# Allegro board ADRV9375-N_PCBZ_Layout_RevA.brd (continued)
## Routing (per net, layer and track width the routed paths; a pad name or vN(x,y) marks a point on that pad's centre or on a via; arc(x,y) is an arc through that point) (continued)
SNRXA-: length 16.3
  TOP w0.254: U101.D4 v6(30.84,43.58)
  L10_SIG w0.091: v6(30.84,43.58) 31.12,43.58 arc(31.24,43.53) 31.28,43.42 arc(31.29,43.36) 31.33,43.31 31.38,43.26 arc(31.42,43.16) 31.38,43.07 31.28,42.97 arc(31.22,42.88) 31.2,42.78 arc(31.21,42.74) 31.23,42.71 31.42,42.51 arc(31.46,42.46) 31.47,42.4 arc(31.46,42.31) 31.41,42.24 31.25,42.08 arc(31.21,42.03) 31.2,41.96 arc(31.16,41.78) 31.06,41.62 arc(30.92,41.53) 30.76,41.5 30.6,41.5 arc(30.13,41.3) 29.93,40.83 29.93,36.18 arc(29.84,35.73) 29.59,35.35 29.53,35.29 arc(29.14,34.81) 28.87,34.25 arc(28.41,32.9) 28,31.53 arc(27.91,31.35) v5(27.75,31.22)
  BOTTOM w0.203: C223.2 27.19,29.74 arc(27.3,29.82) 27.37,29.94 ; C224.2 L224.2 27.71,30.93 arc(27.74,31.07) v5(27.75,31.22)
SPI_CLK: length 112.3
  TOP w0.254: U405.3 120.14,60.64 121.68,59.1 121.68,58.09 120.48,56.9 TP802.1 ; U101.K9 v6(36.44,48.38)
  TOP w0.305: TP802.1 121.34,54.91 129.9,54.91 131.17,56.17 R804.1
  L7_SIG w0.114: TP802.1 119,54.28 104.66,54.28 100.72,58.21 93.1,58.21 v8(92.85,57.96)
  L8_SIG w0.114: v6(36.44,48.38) 36.69,48.38 37.08,47.99 41.22,47.99 41.41,48.18 46,48.18 47.19,49.37 49.84,49.37 50.68,50.21 65.67,50.21 73.42,57.96 v8(92.85,57.96)
SPI_CLK_9528: length 44.4
  TOP w0.203: U405.12 120.14,66.45 v1(119.77,66.09)
  L7_SIG w0.114: v1(119.77,66.09) 119.35,66.51 119.35,66.51 119.05,66.81 119.05,66.81 119.01,66.85 118.75,66.85 116.28,69.33 96.08,69.33 93.74,71.67 84.47,71.67 83.56,70.76 82.44,70.76 v1(82.21,70.99)
  BOTTOM w0.254: U401.22 83.47,70.83 83.38,70.74 82.46,70.74 v1(82.21,70.99)
SPI_CS0: length 120.1
  TOP w0.254: R811.1 R808.2 138.55,55.23 138.89,55.57 v2(139.1,55.57) ; U101.K10 v6(36.44,49.18) ; TP813.1 119.9,58.69 118.65,59.94 117.33,59.94 116.71,60.56 U403.7
  L7_SIG w0.114: TP813.1 119.34,57.54 116.88,57.54 115.13,55.8 105.67,55.8 101.86,59.61 89.42,59.61 v8(89.04,59.23)
  L8_SIG w0.114: v6(36.44,49.18) 36.84,49.58 40.01,49.58 40.52,50.08 43.11,50.08 43.27,49.93 43.61,49.93 43.9,50.21 45.2,50.21 46.85,51.86 63.89,51.86 72.27,60.24 85.35,60.24 86.37,59.23 v8(89.04,59.23)
  L8_SIG w0.254: TP813.1 122.99,56.18 138.49,56.18 v2(139.1,55.57)
SPI_CS1: length 37
  TOP w0.254: 121.44,63.18 U405.5 ; U403.1 117.21,64.54 117.48,64.82
  TOP w0.305: 117.48,64.82 117.7,65.03 119.58,65.03 121.44,63.18 121.93,63.67 124.09,63.67 TP814.1 127.34,62.4 127.52,62.23 130.41,62.23 130.74,62.56 136.69,62.56 137.12,62.12 137.12,52.75 137.5,52.37 138.21,52.37 138.55,52.71 R809.2 R812.1
SPI_CS_9528: length 47
  TOP w0.203: U405.10 121.44,66.07 v1(121.68,65.83)
  L7_SIG w0.114: v1(81.7,70.25) 93.12,70.25 95.2,68.18 115.77,68.18 118.75,65.2 121.04,65.2 v1(121.68,65.83)
  BOTTOM w0.254: v1(81.7,70.25) 83.62,70.25 83.69,70.33 83.78,70.33 U401.21
SPI_DIN: length 114.3
  TOP w0.254: U405.4 120.79,60.88 123,58.66 TP801.1 ; U101.J9 v6(35.64,48.38)
  TOP w0.305: TP801.1 125.39,56.68 129.45,56.68 130.14,57.37 R805.1
  L7_SIG w0.114: v1(83.96,59.36) 84.03,59.36 85.56,60.88 87.17,60.88 87.17,60.89 87.6,60.89 87.6,60.88 96.59,60.88 96.97,60.5 102.24,60.5 106.18,56.56 113.93,56.56 117.4,60.03 122.03,60.03 TP801.1
  L8_SIG w0.114: v1(83.96,59.36) 83.91,59.4 72.96,59.4 64.65,51.1 47,51.1 45.27,49.37 40.95,49.37 40.34,48.76 36.03,48.76 v6(35.64,48.38)
SPI_DIN_9528: length 43.6
  TOP w0.203: U405.11 v1(120.79,66.34)
  L7_SIG w0.114: v1(120.79,66.34) 120.79,66.47 116.85,70.4 96.53,70.4 93.86,73.07 85.02,73.07 v1(83.28,71.33)
  BOTTOM w0.254: U401.23 83.68,71.33 v1(83.28,71.33)
SPI_DOUT: length 31.6
  TOP w0.203: TP809.1 117.59,58.69 ; 116.2,61.33 U403.6
  TOP w0.254: R806.1 136.06,55.72 136.06,55.71 136.06,55.45 135.47,54.86 130.95,54.86 130.23,54.15 119.47,54.15 118.66,54.96 118.66,57.62 116.19,60.09 116.19,61.32 116.21,61.35 U403.3
SPI_DOUT_9370: length 91.9
  TOP w0.254: U101.J10 v6(35.64,49.18) ; TP402.1 116.07,57.26 R427.2
  L7_SIG w0.097: 39.89,46.39 39.49,46.39
  L7_SIG w0.114: 39.49,46.39 37.95,46.39 37.7,46.64 37.7,47.06 37.58,47.19 37.08,47.19 36.85,47.42 36.85,47.74 36.55,48.04 36.3,48.04 36.1,48.24 36.1,48.66 35.64,49.13 v6(35.64,49.18) ; 39.89,46.39 42.88,46.39 43.41,46.92 44.45,46.92 45.18,46.19 48.52,46.19 48.61,46.11 75.41,46.11 77.1,47.8 77.63,47.8 79.64,49.81 v1(79.64,50.08)
  BOTTOM w0.394: TP402.1 111.83,50.08 v1(79.64,50.08)
SPI_DOUT_9528: length 40.5
  TOP w0.254: R426.2 111.83,71.17 101.36,71.17 TP401.1
  L7_SIG w0.114: TP401.1 96.91,71.55 94.12,74.34 85.25,74.34 v1(82.56,71.65)
  BOTTOM w0.254: v1(82.56,71.65) 82.83,71.91 83.59,71.91 83.67,71.83 83.81,71.83 U401.24
STATUS_0: length 25.1
  L5_SIG w0.114: v1(96.53,79.96) 96.19,80.3 77.85,80.3 v1(77.25,79.7)
  BOTTOM w0.254: U401.55 94.81,77.83 95.9,78.92 95.9,79.32 v1(96.53,79.96) ; R418.1 97.17,79.96
  BOTTOM w0.305: v1(77.25,79.7) 76.64,79.7 76.63,79.69 U402.1
  BOTTOM w0.394: 97.17,79.96 v1(96.53,79.96)
STATUS_1: length 24.5
  L5_SIG w0.114: v1(77.25,78.38) 77.76,78.89 v1(96.53,78.89)
  BOTTOM w0.203: R419.1 97.17,78.89
  BOTTOM w0.254: v1(96.53,78.89) 96.53,78.83 95.03,77.33 U401.56
  BOTTOM w0.305: v1(77.25,78.38) 76.64,78.38 76.63,78.39 U402.3
  BOTTOM w0.394: 97.17,78.89 v1(96.53,78.89)
SYNCINB0+: length 150.5
  TOP w0.254: U101.M4 v6(38.04,43.58)
  L7_SIG w0.091: v6(38.04,43.58) 38.04,43.25 37.71,42.91 37.71,41.85 37.93,41.62 39.84,41.62 40.77,40.68 44.84,40.68 48.14,37.38 59.68,37.38 60.57,38.27 105.19,38.27 110.14,33.32 111.79,33.32 113.19,31.92 116.24,31.92 119.66,28.49 126.63,28.49 127.14,29 ; 127.14,29 127.77,29.64 132.45,29.64 136.77,33.96 137.78,33.96 139.91,36.09 139.91,39.2 141.36,40.65 141.97,40.65 143.75,42.43 143.75,60.77 143.14,61.39 137.02,61.39 v2(136.56,61.85) ; 127.14,29 TP807.1
  BOTTOM w0.203: P801.G9 v2(136.56,61.85)
SYNCINB0-: length 150.5
  TOP w0.254: U101.M3 v6(38.04,42.78)
  L7_SIG w0.091: 127.02,29.24 126.96,29.18 126.96,29.18 126.52,28.75 119.77,28.75 116.34,32.18 113.29,32.18 111.9,33.57 110.25,33.57 105.29,38.53 60.46,38.53 59.57,37.64 48.25,37.64 44.95,40.94 40.87,40.94 40.09,41.72 40.09,42.16 39.93,42.32 38.14,42.32 38.04,42.42 v6(38.04,42.78) ; 127.02,29.24 126.89,29.24 126.14,29.99 TP808.1 ; 127.02,29.24 127.67,29.89 132.34,29.89 136.66,34.21 137.68,34.21 139.66,36.19 139.66,39.31 141.26,40.91 141.87,40.91 143.5,42.54 143.5,60.67 143.03,61.14 136.92,61.14 136.66,61.39 135.9,61.39 135.77,61.26 135.77,60.58 135.9,60.45 136.44,60.45 136.56,60.58 v2(136.56,60.58)
  BOTTOM w0.203: P801.G10 v2(136.56,60.58)
SYNCINB1+: length 108.7
  TOP w0.254: U101.L4 v6(37.24,43.58)
  L7_SIG w0.091: 116.02,34.14 115.71,33.83 114.54,33.83 113.4,34.97 111.01,34.97 109.02,36.96 108.88,36.96 105.28,40.56 49.54,40.56 48.4,41.7 46.08,41.7 44.05,43.73 40.01,43.73 39.77,43.98 38.62,43.98 38.36,44.24 38.36,44.51 38.17,44.7 37.9,44.7 37.66,44.46 37.66,44.12 37.33,43.78 37.33,43.66 v6(37.24,43.58) ; 116.02,34.14 116.02,34.28 TP810.1 ; 116.02,34.14 121.19,39.32 124.82,39.32 125.02,39.12 125.79,39.12 126.42,39.75 134.79,39.75 v2(135.29,40.26)
  BOTTOM w0.203: P801.G27 v2(135.29,40.26)
SYNCINB1-: length 108.8
  TOP w0.254: U101.L3 v6(37.24,42.78)
  L7_SIG w0.091: v6(37.24,42.78) 37.24,43.12 37.56,43.44 37.56,43.44 37.58,43.46 37.58,43.68 37.8,43.9 38.17,43.9 38.51,43.56 38.51,43.44 38.73,43.23 39.76,43.23 40.01,43.48 43.95,43.48 45.98,41.45 48.29,41.45 49.43,40.31 105.18,40.31 108.78,36.7 108.92,36.7 110.9,34.72 113.29,34.72 114.44,33.57 115.81,33.57 116.84,34.6 ; v2(135.29,38.99) 134.79,39.5 126.53,39.5 125.9,38.86 124.91,38.86 124.71,39.06 121.3,39.06 116.84,34.6 ; 116.84,34.6 117.55,33.89 TP811.1
  BOTTOM w0.203: P801.G28 v2(135.29,38.99)
SYNCOUTB0+: length 115.2
  TOP w0.203: U101.M13 v6(37.24,51.58)
  L8_SIG w0.091: TP805.1 127.9,66.26 127.9,65.2 ; v2(134.02,65.67) 133.55,65.2 127.9,65.2 ; 127.9,65.2 125.49,65.2 120.53,70.15 86.75,70.15 84.34,72.56 77.23,72.56 76.08,71.42 76.08,70.66 71.64,66.21 71.64,61.62 70.39,60.37 58.56,60.37 51.57,53.39 45.86,53.39 44.15,51.68 40.19,51.68 39.88,51.99 38.72,51.99 38.42,52.29 37.78,52.29 37.54,52.05 37.54,51.74 37.38,51.58 v6(37.24,51.58)
  BOTTOM w0.203: P801.H7 134.02,65.66 v2(134.02,65.67)
SYNCOUTB0-: length 115.3
  TOP w0.203: U101.M14 v6(38.04,51.58)
  L8_SIG w0.091: 127.9,64.94 127.9,63.79 TP806.1 ; 127.9,64.94 133.43,64.94 v2(134.02,64.35) ; 127.9,64.94 125.38,64.94 120.43,69.9 86.64,69.9 84.23,72.31 77.33,72.31 76.34,71.32 76.34,70.55 71.89,66.11 71.89,61.51 70.49,60.12 58.66,60.12 51.68,53.13 45.96,53.13 44.26,51.43 40.14,51.43 39.94,51.23 38.67,51.23 38.46,51.43 38.46,51.88 38.32,52.03 37.89,52.03 37.8,51.94 37.8,51.74 37.96,51.58 v6(38.04,51.58)
  BOTTOM w0.203: v2(134.02,64.35) 134.06,64.35 P801.H8
SYSREF_IN+: length 78.5
  TOP w0.254: U101.K3 v6(36.44,42.78)
  L7_SIG w0.091: v6(36.44,42.78) 35.96,43.25 35.38,43.25 35.06,43.58 34.68,43.95 34.68,45.57 34.51,45.74 34.51,48.6 34.23,48.88 33.9,48.88 33.71,49.07 33.71,49.28 33.34,49.65 33.1,49.65 32.91,49.84 32.91,50.2 32.65,50.47 32.65,51.23 35.7,54.28 37.58,54.28 39.87,56.56 41.05,56.56 43.19,58.7 43.19,62.02 46.75,65.57 46.75,66.09 48.9,68.25 58.32,68.25 59.59,69.52 64.62,69.52 66.02,70.91 70.11,70.91 72.29,73.09 72.29,73.31 73.33,74.34 75.47,74.34 75.83,74.7 75.83,75.38 75.56,75.65 75.3,75.65 v1(75.02,75.37)
  BOTTOM w0.203: U401.28 84.06,73.83 83.68,73.83 83.61,73.9 82.81,73.9 81.12,75.6 80.57,75.6 ; R424.2 80.57,75.6 ; 80.57,75.6 75.25,75.6 v1(75.02,75.37)
SYSREF_IN-: length 78.8
  TOP w0.254: U101.K4 v6(36.44,43.58)
  L7_SIG w0.091: v6(36.44,43.58) 36.44,43.82 36.36,43.9 35.5,43.9 35.36,43.76 35.24,43.76 34.93,44.06 34.93,45.51 35.19,45.77 35.19,48.49 34.97,48.7 34.77,48.7 34.36,49.11 34.36,49.34 34.17,49.53 33.94,49.53 33.56,49.91 33.56,50.11 33.37,50.3 33.17,50.3 32.9,50.57 32.9,51.12 35.8,54.02 37.69,54.02 39.98,56.31 41.16,56.31 43.44,58.59 43.44,61.91 47,65.47 47,65.98 49.01,67.99 58.43,67.99 59.7,69.26 64.73,69.26 66.12,70.66 70.22,70.66 72.55,72.99 72.55,73.2 73.43,74.09 75.57,74.09 76.08,74.6 76.08,75.48 75.67,75.9 75.3,75.9 v1(75.02,76.18)
  BOTTOM w0.203: 80.57,75.95 75.25,75.95 v1(75.02,76.18) ; 80.57,75.95 R424.1 ; 80.57,75.95 81.27,75.95 82.96,74.26 83.58,74.26 83.66,74.33 84.12,74.33 U401.29
TEST: length 169
  TOP w0.254: U101.J6 v6(35.64,45.98)
  TOP w0.394: R504.1 R503.2 143.55,24.35 144.95,25.75 144.95,33.16 143.61,34.5 143.61,40.79 142.12,42.27 142.12,43.33 140.98,44.48 140.98,51.16 142.34,52.52 142.34,58.59 v2(141.62,59.31) 141.31,59.61 R810.1
  L7_SIG w0.114: v6(35.64,45.98) 35.97,45.64 37.47,45.64 37.73,45.89 38.44,45.89 38.7,45.64 45.73,45.64 46.87,44.5 51.55,44.5 51.68,44.63 53.22,44.63 53.86,43.99 54.49,43.99 54.5,44 76.11,44 79.44,47.32 79.8,47.32 82.56,50.08 82.56,51.97 83.34,52.75 84.21,52.75 85.13,53.67 85.13,54.55 86.26,55.67 87.64,55.67 89,57.03 100.63,57.03 104.15,53.51 121.76,53.51 127.39,59.15 133.31,59.15 133.67,58.79 141.1,58.79 v2(141.62,59.31)
TRI_STATE: length 5.4
  BOTTOM w0.394: Y401.2 Y402.2 122.22,73.96 122.29,73.9 R409.2 R408.1
TX1_ENABLE: length 58.8
  TOP w0.254: U101.M6 v6(38.04,45.18)
  TOP w0.305: R507.1 73.61,65.01 P501.9
  L5_SIG w0.114: P501.9 72.53,63.8 72.53,59.86 69.51,56.85 44.74,56.85 44.48,57.1 44.06,57.1 43.58,56.63 41.73,56.63 40.56,55.45 40.56,55.45 39.7,54.59 37.54,54.59 36.65,53.7 36.65,52.64 36.77,52.52 36.77,52.2 36.58,52 36.39,52 36.1,51.72 36.1,47.44 36.3,47.24 36.49,47.24 36.77,46.95 36.77,45.96 37.22,45.51 37.7,45.51 v6(38.04,45.18)
  BOTTOM w0.203: 73.67,66.42 P501.9
TX2_ENABLE: length 53
  TOP w0.254: U101.M8 v6(38.04,47.58)
  TOP w0.305: R506.1 73.73,62.34 P501.10
  L5_SIG w0.114: v6(38.04,47.58) 37.79,47.58 37.37,47.99 37.08,47.99 36.84,48.23 36.84,51.65 37.1,51.91 37.11,51.91 37.22,52.03 37.22,52.69 37.14,52.78 37.14,53.59 37.69,54.14 40.13,54.14 41.16,55.16 44.46,55.16 44.84,55.55 68.97,55.55 73.67,60.24 P501.10
  BOTTOM w0.203: 73.67,60.93 P501.10
TX_EXTLO+: length 12
  TOP w0.203: U101.E12 v6(32.44,49.98)
  L10_SIG w0.091: v5(29.14,59.52) arc(29.1,59.21) 29.17,58.91 arc(29.28,58.49) 29.31,58.05 arc(29.32,57.79) 29.37,57.55 arc(29.6,56.43) 29.71,55.29 arc(29.85,53.93) 30.18,52.59 arc(30.31,52.3) 30.51,52.04 arc(30.61,51.98) 30.71,51.96 30.84,51.96 arc(31.11,51.85) 31.22,51.58 arc(31.23,51.52) 31.27,51.47 31.41,51.32 arc(31.58,51.07) 31.64,50.78 arc(31.87,50.21) v6(32.44,49.98)
  BOTTOM w0.203: C336.2 v5(29.14,59.52)
TX_EXTLO-: length 11.9
  TOP w0.203: U101.E11 v6(31.64,49.98)
  L10_SIG w0.091: v6(31.64,49.98) 31.5,49.98 arc(31.42,50.01) 31.39,50.08 31.38,50.77 arc(31.38,50.77) 31.38,50.78 arc(31.34,50.97) 31.23,51.14 31.21,51.16 arc(31.16,51.19) 31.11,51.2 30.82,51.2 arc(30.59,51.3) 30.49,51.53 arc(30.46,51.69) 30.37,51.83 30.34,51.86 arc(30.1,52.16) 29.93,52.51 arc(29.6,53.88) 29.45,55.28 arc(29.35,56.39) 29.12,57.48 arc(29.07,57.77) 29.06,58.05 arc(29.01,58.58) 28.81,59.07 arc(28.57,59.25) v5(28.28,59.21)
  BOTTOM w0.203: C337.2 v5(28.28,59.21)
UNNAMED_3_CAP_I2_N1: length 2.5
  TOP w0.203: C204.2 L204.2 ; 21.15,51.71 20.5,51.71 19.87,51.71 ; 21.15,51.71 arc(21.4,51.79) R206.1 arc(21.4,51.79) 21.15,51.71
UNNAMED_3_CAP_I3_N1: length 3.7
  TOP w0.203: 21.15,51.36 20.52,51.36 19.87,51.36 20.52,51.36 21.15,51.36 ; 21.15,51.36 arc(21.4,51.28) C205.1 arc(21.4,51.28) 21.15,51.36 ; C204.1 L204.1
UNNAMED_3_CAP_I11_N1: length 15.4
  TOP w0.127: L200.2 C200.1 ; L201.2 C201.1
  TOP w0.394: C201.1 C200.1 12.73,53.97 10.69,56.01 arc(7.18,58.36) 3.03,59.18 J200.1
UNNAMED_3_CAP_I74_N2: length 2.4
  TOP w0.127: L201.1 C201.2 ; 15.31,51.56 C202.1
  TOP w0.203: R202.1 16.11,50.69
  TOP w0.394: C201.2 C202.1 15.5,51.2 arc(15.64,51.06) 15.79,50.93 arc(15.94,50.8) 16.11,50.69
UNNAMED_3_CAP_I79_N1: length 1.5
  TOP w0.394: T200.2 18.58,49.61 R203.1
UNNAMED_3_CAP_I109_N1: length 1.9
  TOP w0.203: C213.1 L213.1 ; 19.87,41.84 20.52,41.84 21.14,41.84 arc(21.4,41.76) R214.1
UNNAMED_3_CAP_I109_N2: length 1.9
  TOP w0.203: 19.87,42.2 20.5,42.2 21.14,42.2 arc(21.4,42.27) C215.1 ; C213.2 L213.2
UNNAMED_3_CAP_I115_N1: length 14.2
  TOP w0.127: 13.59,38.45 C208.1 ; R209.1 L209.2
  TOP w0.394: J201.1 5.42,35.31 arc(9.78,36.14) C208.1 R209.1
UNNAMED_3_CAP_I115_N2: length 2.3
  TOP w0.127: L211.2 C211.1
  TOP w0.203: 16.11,41.17 C241.1 16.11,41.07
  TOP w0.394: R209.2 C211.1 15.5,40.56 arc(15.64,40.7) 15.79,40.83 arc(15.94,40.96) 16.11,41.07
UNNAMED_3_CAP_I126_N1: length 7.9
  BOTTOM w0.127: C217.1 L217.2
  BOTTOM w0.394: J202.1 21.88,15.48 arc(22.07,17.11) 22.52,18.7 C217.1 23.53,21.5
UNNAMED_3_CAP_I126_N2: length 2.3
  BOTTOM w0.127: L219.2 C219.1
  BOTTOM w0.203: 24.44,23.98 C242.1
  BOTTOM w0.394: 24.44,23.98 C219.1 C218.2
UNNAMED_3_CAP_I127_N1: length 1.5
  BOTTOM w0.394: T202.2 R220.1
UNNAMED_3_CAP_I137_N1: length 1.9
  BOTTOM w0.203: 26.76,27.23 26.99,27.84 27.2,28.43 arc(27.28,28.57) 27.4,28.67 arc(27.5,28.71) 27.6,28.72 ; C221.1 L221.1
UNNAMED_3_CAP_I137_N2: length 1.9
  BOTTOM w0.203: 26.43,27.35 26.64,27.94 26.87,28.55 arc(26.88,28.81) C223.1 ; C221.2 L221.2
UNNAMED_3_CAP_I141_N1: length 1.9
  BOTTOM w0.203: C229.1 L229.2 ; 22.2,57.06 22.56,56.55 22.93,56.01 arc(23.14,55.85) R230.1
UNNAMED_3_CAP_I141_N2: length 1.9
  BOTTOM w0.203: 21.91,56.86 22.28,56.32 22.64,55.81 arc(22.72,55.56) C231.1 ; C229.2 L229.1
UNNAMED_3_CAP_I162_N1: length 20.6
  BOTTOM w0.394: J203.1 2.76,71.12 arc(6.67,70.69) 10.48,69.66 arc(14.88,67.3) C225.1 R226.1
UNNAMED_3_CAP_I162_N2: length 2.1
  BOTTOM w0.203: 20.58,60.63 C243.1
  BOTTOM w0.394: R226.2 C227.1 20.58,60.63
UNNAMED_3_CAP_I167_N1: length 1.5
  BOTTOM w0.394: 22.05,58.53 C228.1
UNNAMED_3_CAP_I173_N1: length 19.7
  BOTTOM w0.394: 17.13,31.13 17.09,31.06 arc(14.05,27.65) 10.3,25.03 arc(6.82,23.72) 3.11,23.37 J204.1 ; 17.13,31.13 C233.1 ; 17.13,31.13 C234.1
UNNAMED_3_CAP_I173_N2: length 2.1
  BOTTOM w0.203: 19.11,33.96 R210.1
  BOTTOM w0.394: C234.2 C235.1 19.11,33.96
UNNAMED_3_CAP_I178_N2: length 1.5
  BOTTOM w0.394: T204.2 C236.2
UNNAMED_3_CAP_I188_N1: length 1.9
  BOTTOM w0.203: 21.91,36.69 22.27,37.21 22.64,37.74 arc(22.72,37.99) C238.1 ; C237.1 L237.2
UNNAMED_3_CAP_I188_N2: length 1.9
  BOTTOM w0.203: C237.2 L237.1 ; 22.2,36.49 22.57,37.03 22.93,37.54 arc(23.14,37.7) C239.1
UNNAMED_3_CAP_I191_N1: length 1.5
  TOP w0.394: R212.1 18.58,40.23 T201.2
UNNAMED_3_CAP_I192_N2: length 1.1
  TOP w0.203: 17.42,50.64 T200.1 ; R202.2 16.95,50.64
  TOP w0.394: 16.95,50.64 17.42,50.64 ; 17.59,50.65 17.59,50.64
UNNAMED_3_CAP_I194_N2: length 1.1
  TOP w0.203: C241.2 16.95,41.12 ; 17.42,41.12 T201.1
  TOP w0.394: 16.95,41.12 17.42,41.12
UNNAMED_3_CAP_I197_N2: length 1.1
  BOTTOM w0.127: C242.2 24.77,24.83
  BOTTOM w0.203: T202.1 24.95,25.4
  BOTTOM w0.394: 24.77,24.83 24.95,25.4
UNNAMED_3_CAP_I199_N2: length 1.1
  BOTTOM w0.127: 21.09,59.86 C243.2
  BOTTOM w0.203: T203.1 21.45,59.39
  BOTTOM w0.394: 21.45,59.39 21.09,59.86
UNNAMED_3_CAP_I201_N2: length 1.1
  BOTTOM w0.127: 19.66,34.69 R210.2
  BOTTOM w0.203: T204.1 19.98,35.19
  BOTTOM w0.394: 19.98,35.19 19.66,34.69
UNNAMED_4_CAP_I388_N1: length 0.9
  BOTTOM w0.203: 22.6,46.43 23.09,46.43 arc(23.28,46.35) C333.1
UNNAMED_4_CAP_I389_N1: length 0.9
  BOTTOM w0.203: 22.6,46.79 23.09,46.79 arc(23.28,46.87) C332.1
UNNAMED_4_CAP_I525_N1: length 2.1
  TOP w0.127: L301.2 R301.1 ; C305.2 33.92,61.82
  TOP w0.394: 33.92,61.82 C323.1 R301.1
UNNAMED_4_CAP_I526_N1: length 16.4
  TOP w0.127: L301.1 R301.2
  TOP w0.203: C324.1 33.91,65.41
  TOP w0.394: J305.1 33.91,65.41 R301.2
UNNAMED_4_CAP_I531_N1: length 15.2
  TOP w0.394: C302.2 C329.1 J306.1
UNNAMED_4_CAP_I533_N1: length 2
  TOP w0.203: 35.76,31.73 R304.2
  TOP w0.394: C302.1 C328.1 35.76,31.73
UNNAMED_4_CAP_I561_N1: length 3.6
  BOTTOM w0.203: C331.1 20.56,47.25 T307.1
  BOTTOM w0.394: 19.36,47.24 20.56,47.25 ; 19.36,47.24 C331.1 ; 19.36,47.24 R312.2
UNNAMED_4_CAP_I563_N1: length 16.6
  BOTTOM w0.394: J307.1 C330.1 R312.1
UNNAMED_4_CAP_I601_N1: length 3.7
  BOTTOM w0.203: C335.1 27.93,63.37 T308.1
  BOTTOM w0.394: 27.51,64.54 27.93,63.37 ; 27.51,64.54 R313.2 ; 27.51,64.54 C335.1
UNNAMED_4_CAP_I603_N1: length 15.7
  BOTTOM w0.394: J308.1 21.88,79.08 arc(22.29,77.11) 23.05,75.25 arc(24.76,71.71) 26.22,68.06 C334.1 R313.1
UNNAMED_4_CAP_I696_N1: length 0.9
  BOTTOM w0.203: 28.2,61.26 28.37,60.81 arc(28.51,60.65) 28.73,60.64
UNNAMED_4_CAP_I697_N1: length 0.9
  BOTTOM w0.203: 27.87,61.14 28.03,60.69 arc(28.03,60.47) C337.1
UNNAMED_5_CAP_I803_N2: length 1
  BOTTOM w0.254: R415.1 89.85,65.59 89.86,65.58 C411.2
UNNAMED_5_CAP_I905_N1: length 6.4
  BOTTOM w0.394: C401.1 105.81,62.02 R401.2 107.27,60.57 J401.1
UNNAMED_5_CAP_I905_N2: length 1.6
  BOTTOM w0.394: T401.4 C401.2
UNNAMED_5_CAP_I916_N1: length 63
  BOTTOM w0.203: C408.1 88.76,62.37 88.43,62.04 88.43,61.31 89.65,60.09 96.93,60.09 100.87,56.16 113.65,56.16 115.6,58.11 115.6,63.27 113,65.87 106.01,65.87 102.65,69.23 102.65,72.66 104.14,74.14 107.51,74.14 107.96,73.69 R413.1 R411.2
UNNAMED_5_CMOSNC7WV125K8X_I90_1: length 3.6
  TOP w0.203: 115.71,61.09 U403.5
  TOP w0.254: R427.1 115.33,60.37 115.71,60.76 115.71,61.09
UNNAMED_5_CMOSNC7WV125K8X_I90_A: length 1.7
  TOP w0.254: U403.2 116.71,64.03 116.7,64.05 R426.1
UNNAMED_5_DIOLED_I865_P: length 2.5
  TOP w0.305: v1(70.24,78.29) 69.91,77.96 D401.A
  BOTTOM w0.305: R420.2 v1(70.24,78.29)
UNNAMED_5_DIOLED_I866_P: length 2.5
  TOP w0.305: v1(70.24,79.82) 69.94,80.12 D402.A
  BOTTOM w0.305: v1(70.24,79.82) R421.2
UNNAMED_5_NC7WZ17P6X_I868_Y1: length 1.9
  BOTTOM w0.305: U402.6 73.14,79.69 73.01,79.82 R421.1
UNNAMED_5_NC7WZ17P6X_I868_Y2: length 1.9
  BOTTOM w0.305: U402.4 73.24,78.39 73.14,78.29 R420.1
UNNAMED_5_RES_I897_N2: length 63
  BOTTOM w0.203: R414.1 87.74,62.37 88.07,62.04 88.07,61.16 89.5,59.74 96.78,59.74 100.72,55.8 113.8,55.8 115.96,57.96 115.96,63.41 113.14,66.23 106.16,66.23 103.01,69.38 103.01,70.93 103.45,71.37 104.75,71.37 105.78,70.35 107.62,70.35 107.96,70.68 R412.2 R410.2
UNNAMED_5_RES_I907_N2: length 1.6
  BOTTOM w0.394: T401.5 R402.2
UNNAMED_6_AD9370V2_I826_DEVCL_1: length 1.2
  TOP w0.203: U101.E7 v5(32.44,46.78)
  BOTTOM w0.203: C502.2 32.34,47 arc(32.37,46.88) v5(32.44,46.78)
UNNAMED_6_AD9370V2_I826_DEVCLKI: length 1.2
  TOP w0.203: U101.E8 v5(31.64,46.78)
  BOTTOM w0.203: C501.2 31.71,46.95 arc(31.69,46.86) v5(31.64,46.78)
UNNAMED_6_AD9370V2_I826_RBIAS: length 2.5
  TOP w0.203: R505.2 28.89,53.52 U101.C14
UNNAMED_6_AD9370V2_I832_SERDI_1: length 113.1
  TOP w0.203: U101.P11 v6(39.62,50.05)
  L5_SIG w0.091: v6(39.62,50.05) arc(39.88,50.23) 40.19,50.29 40.55,50.29 arc(42.45,49.95) 44.12,48.97 arc(50.63,45.15) 58.08,43.88 110.04,43.88 arc(116.17,43) 121.8,40.45 arc(127.49,37.86) 133.67,36.94 141.44,36.94 arc(142.94,37.32) 144.08,38.37 144.49,38.99 arc(145.48,39.85) 146.77,40.07 arc(147.05,40.01) v2(147.32,39.88)
  BOTTOM w0.203: C507.2 v2(147.32,39.88)
UNNAMED_6_AD9370V2_I832_SERDI_2: length 117
  TOP w0.203: v6(39.63,51.64) 39.63,51.57 U101.P13 ; 142.47,70.3 v6(142.91,70.74)
  L10_SIG w0.091: v6(142.91,70.74) arc(142.75,71.1) 142.38,71.25 140.39,71.25 arc(138.93,70.99) 137.69,70.17 arc(136.28,68.13) 135.54,65.76 arc(134.51,61.89) 132.63,58.34 arc(129.4,54.97) 125.23,52.86 arc(122.37,51.71) 119.71,50.15 arc(115.87,48.26) 111.63,47.62 55.41,47.62 arc(50.9,48.26) 46.72,50.08 arc(43.69,51.39) 40.42,51.83 40,51.83 arc(39.79,51.78) v6(39.63,51.64)
UNNAMED_6_AD9370V2_I832_SERDI_3: length 115.5
  TOP w0.203: v6(38.84,49.18) U101.N10
  L5_SIG w0.091: v2(147.32,34.8) arc(147.19,34.98) 146.98,35.05 146.51,35.05 arc(145.9,34.96) 145.37,34.64 arc(144.56,33.88) 143.82,33.05 arc(142.74,32.19) 141.39,31.89 133.34,31.89 arc(131.1,32.09) 128.93,32.69 arc(124.24,34.76) 119.79,37.29 arc(115.12,39.41) 110.04,40.14 60.44,40.14 arc(50.8,42.18) 42.9,48.06 arc(41.52,49.08) 39.84,49.45 39.15,49.45 arc(38.94,49.37) v6(38.84,49.18)
  BOTTOM w0.203: C511.2 v2(147.32,34.8)
UNNAMED_6_AD9370V2_I832_SERDI_4: length 114.3
  TOP w0.203: v6(38.84,51.58) U101.N13
  L5_SIG w0.091: v2(147.32,45.72) arc(147.13,45.52) 146.87,45.45 146.49,45.45 arc(145.78,45.29) 145.2,44.84 144.77,44.3 142.97,42.06 arc(140.84,40.37) 138.19,39.76 134.18,39.76 arc(132.37,39.93) 130.62,40.42 arc(127.2,41.96) 123.95,43.81 arc(117.28,46.83) 110.04,47.87 55.54,47.87 arc(51.44,48.34) 47.56,49.75 arc(44.29,50.92) 40.83,51.3 39.26,51.3 arc(39.01,51.38) v6(38.84,51.58)
  BOTTOM w0.203: C514.2 v2(147.32,45.72)
UNNAMED_6_AD9370V2_I832_SERDIN0: length 113
  TOP w0.203: U101.P12 v6(39.58,50.71)
  L5_SIG w0.091: v2(147.32,40.64) arc(147.11,40.39) 146.79,40.32 arc(145.37,40.08) 144.28,39.13 143.87,38.51 arc(142.82,37.55) 141.44,37.2 133.67,37.2 arc(127.56,38.1) 121.94,40.66 arc(116.24,43.25) 110.04,44.13 58.08,44.13 arc(50.72,45.39) 44.28,49.16 arc(42.54,50.19) 40.55,50.55 40.19,50.55 arc(39.87,50.59) v6(39.58,50.71)
  BOTTOM w0.203: C508.2 v2(147.32,40.64)
UNNAMED_6_AD9370V2_I832_SERDIN1: length 117.1
  TOP w0.203: v6(39.64,52.38) U101.P14 ; 142.47,71.57 v6(142.91,72.01)
  L10_SIG w0.091: v6(39.64,52.38) arc(39.77,52.17) 40,52.09 40.42,52.09 arc(43.76,51.63) 46.85,50.29 arc(50.97,48.51) 55.41,47.87 111.63,47.87 arc(115.79,48.51) 119.56,50.36 arc(122.26,51.94) 125.16,53.1 arc(129.25,55.18) 132.42,58.48 arc(134.27,61.98) 135.29,65.8 arc(136.05,68.24) 137.5,70.35 arc(138.83,71.22) 140.4,71.5 142.39,71.5 arc(142.75,71.65) v6(142.91,72.01)
UNNAMED_6_AD9370V2_I832_SERDIN2: length 115.5
  TOP w0.203: v6(38.84,49.98) U101.N11
  L5_SIG w0.091: v6(38.84,49.98) arc(38.94,49.78) 39.15,49.7 39.84,49.7 arc(41.62,49.32) 43.09,48.22 arc(50.91,42.41) 60.44,40.39 110.04,40.39 arc(115.19,39.66) 119.93,37.51 arc(124.36,34.99) 129.02,32.93 arc(131.14,32.34) 133.34,32.14 141.39,32.14 arc(142.63,32.42) 143.62,33.21 arc(144.38,34.06) 145.2,34.84 arc(145.82,35.19) 146.52,35.31 146.98,35.31 arc(147.19,35.38) v2(147.32,35.56)
  BOTTOM w0.203: C512.2 v2(147.32,35.56)
UNNAMED_6_AD9370V2_I832_SERDIN3: length 114.3
  TOP w0.203: v6(38.84,50.78) U101.N12
  L5_SIG w0.091: v6(38.84,50.78) arc(39.01,50.97) 39.26,51.05 40.83,51.05 arc(44.23,50.67) 47.45,49.52 arc(51.38,48.1) 55.54,47.62 110.04,47.62 arc(117.21,46.59) 123.81,43.6 arc(127.09,41.73) 130.53,40.19 arc(132.32,39.68) 134.18,39.51 138.19,39.51 arc(140.95,40.14) 143.17,41.9 144.96,44.14 145.4,44.68 arc(145.89,45.06) 146.49,45.19 146.86,45.19 147,45.19 arc(147.2,45.13) v2(147.32,44.96)
  BOTTOM w0.203: C513.2 v2(147.32,44.96)
UNNAMED_6_AD9370V2_I832_SERDO_1: length 123.3
  TOP w0.203: U101.P6 v6(39.56,45.25)
  L10_SIG w0.091: v6(39.56,45.25) arc(39.77,45.45) 40.05,45.53 40.28,45.53 arc(45.36,45.58) 50.43,45.73 arc(52.96,45.79) 55.49,45.75 111.63,45.75 arc(116.12,46.39) 120.25,48.26 arc(126.72,51.2) 133.77,52.22 135.45,52.22 arc(136.81,52.78) 137.38,54.15 137.38,61.79 arc(138.07,64.18) 139.95,65.82 arc(141.81,67.04) 143.25,68.74 arc(144.73,70.12) 146.69,70.6 146.98,70.6 146.99,70.6 arc(147.2,70.54) v2(147.32,70.36)
  BOTTOM w0.203: C515.2 v2(147.32,70.36)
UNNAMED_6_AD9370V2_I832_SERDO_2: length 127
  TOP w0.203: U101.P4 v6(39.56,43.65)
  L10_SIG w0.091: v2(147.32,65.28) arc(147.2,65.49) 146.96,65.57 146.95,65.57 arc(146.7,65.52) 146.48,65.38 146.42,65.31 146.42,65.31 arc(144.51,62.49) 143.84,59.14 143.84,51.45 arc(143.67,50.21) 143.15,49.08 arc(143.14,49.06) 143.14,49.05 143.13,49.04 143.07,48.97 142.25,48.21 141.95,48.21 141.86,48.3 141.49,48.3 141.22,48.03 141.22,47.86 140.9,47.54 139.16,47.16 133.35,47.16 arc(130.72,46.71) 128.49,45.25 arc(120.75,40.08) 111.63,38.27 63.41,38.27 arc(58.18,38.92) 53.25,40.81 arc(47.34,43.06) 41.05,43.83 39.98,43.83 arc(39.75,43.78) v6(39.56,43.65)
  BOTTOM w0.203: C517.2 v2(147.32,65.28)
UNNAMED_6_AD9370V2_I832_SERDO_3: length 127
  TOP w0.203: U101.P5 v6(39.7,44.32)
  L10_SIG w0.091: v6(39.7,44.32) 39.8,44.23 arc(39.96,44.12) 40.15,44.08 41.05,44.08 arc(47.4,43.31) 53.37,41.03 arc(58.24,39.17) 63.41,38.52 111.63,38.52 arc(120.66,40.32) 128.31,45.43 arc(130.63,46.95) 133.36,47.41 139.13,47.41 140.77,47.77 140.97,47.96 140.97,48.14 141.38,48.55 141.97,48.55 142.06,48.46 142.15,48.46 142.88,49.14 142.92,49.19 143.16,50.03 143.37,50.23 143.37,50.72 143.59,51.49 143.59,59.14 arc(144.28,62.59) 146.24,65.49 146.3,65.55 arc(146.6,65.75) 146.95,65.82 arc(147.16,65.89) v2(147.32,66.04)
  BOTTOM w0.203: C518.2 v2(147.32,66.04)
UNNAMED_6_AD9370V2_I832_SERDO_4: length 119.9
  TOP w0.203: 142.47,63.56 v6(142.91,63.12)
  TOP w0.254: v6(38.84,44.38) U101.N5
  L10_SIG w0.091: v6(38.84,44.38) arc(39.01,44.57) 39.25,44.65 41.89,44.65 arc(47.03,44.33) 52.1,43.38 arc(57.63,42.34) 63.26,42.01 111.63,42.01 arc(118.02,43.07) 123.73,46.14 arc(128.57,48.75) 134,49.65 136.95,49.65 arc(138.86,49.97) 140.58,50.86 arc(141.92,52.46) 142.4,54.5 142.4,61.46 arc(142.36,61.92) 142.21,62.36 142.01,62.83 arc(141.95,63.02) 141.93,63.22 arc(142.09,63.58) 142.47,63.71 arc(142.82,63.51) v6(142.91,63.12)
UNNAMED_6_AD9370V2_I832_SERDO_5: length 119.9
  TOP w0.203: 142.47,64.83 v6(142.91,64.39)
  TOP w0.254: v6(38.84,45.18) U101.N6
  L10_SIG w0.091: v6(142.91,64.39) arc(142.81,64.07) 142.49,63.96 arc(141.92,63.77) 141.68,63.22 arc(141.7,62.97) 141.77,62.73 141.98,62.26 arc(142.11,61.87) 142.15,61.46 142.15,54.5 arc(141.69,52.58) 140.42,51.07 arc(138.78,50.21) 136.94,49.91 134,49.91 arc(128.49,48.99) 123.57,46.34 arc(117.94,43.31) 111.63,42.26 63.26,42.26 arc(57.67,42.59) 52.16,43.62 arc(47.07,44.58) 41.89,44.9 39,44.9 arc(38.84,44.99) v6(38.84,45.18)
UNNAMED_6_AD9370V2_I832_SERDO_6: length 127.4
  TOP w0.254: v6(38.84,43.58) U101.N4
  L10_SIG w0.091: v6(38.84,43.58) arc(38.88,43.39) 39.05,43.3 40.95,43.3 arc(45.52,42.57) 49.64,40.45 arc(55.3,37.57) 61.58,36.65 111.63,36.65 arc(120.44,38.25) 128.13,42.84 arc(130.67,44.33) 133.57,44.82 143.03,44.82 arc(144.36,45.37) 144.91,46.7 144.91,58.27 arc(145.49,59.87) 146.97,60.72 arc(147.17,60.8) v2(147.32,60.96)
  BOTTOM w0.203: C522.2 v2(147.32,60.96)
UNNAMED_6_AD9370V2_I832_SERDO_7: length 127.4
  TOP w0.254: v6(38.84,42.78) U101.N3
  L10_SIG w0.091: v2(147.32,60.2) arc(147.24,60.41) 147.02,60.47 arc(145.69,59.71) 145.16,58.27 145.16,46.7 arc(144.54,45.19) 143.03,44.56 133.56,44.56 arc(130.75,44.09) 128.3,42.64 arc(120.53,38.01) 111.63,36.4 61.58,36.4 arc(55.22,37.33) 49.49,40.25 arc(45.45,42.33) 40.95,43.05 39.36,43.05 arc(39.06,42.98) v6(38.84,42.78)
  BOTTOM w0.203: C521.2 v2(147.32,60.2)
UNNAMED_6_AD9370V2_I832_SERDOUT: length 123.3
  TOP w0.203: U101.P7 v6(39.56,46.05)
  L10_SIG w0.091: v2(147.32,71.12) arc(147.19,70.93) 146.98,70.85 146.7,70.85 arc(144.61,70.34) 143.04,68.87 arc(141.64,67.23) 139.84,66.05 arc(137.86,64.32) 137.12,61.79 137.12,54.15 arc(136.63,52.96) 135.45,52.47 133.77,52.47 arc(126.65,51.45) 120.11,48.47 arc(116.05,46.63) 111.63,46 55.5,46 arc(52.96,46.04) 50.42,45.99 arc(45.35,45.83) 40.28,45.78 40.05,45.78 arc(39.77,45.85) v6(39.56,46.05)
  BOTTOM w0.203: C516.2 v2(147.32,71.12)
UNNAMED_6_CN20PV2_I813_N6: length 4.1
  TOP w0.394: P504.11 49.82,72.47 TP502.1
UNNAMED_6_CN20PV2_I813_N7: length 3.7
  TOP w0.394: P504.13 51.09,71.39 TP501.1
UNNAMED_6_CN20PV2_I813_N9: length 2.4
  TOP w0.394: R525.2 P504.17
UNNAMED_6_CN20PV2_I814_N1: length 71.8
  TOP w0.305: v1(88.06,49.41) 87.96,49.31 87.68,49.31 87.6,49.23 R519.2
  TOP w0.394: P504.2 v1(43.47,80.51)
  L10_SIG w0.114: v1(43.47,80.51) 44.04,81.07 44.98,81.07 45.4,80.64 45.4,80.2 49.92,75.68 49.92,62.02 51.95,59.99 77.73,59.99 82.2,55.52 86.6,55.52 87.47,54.64 87.47,50 v1(88.06,49.41)
UNNAMED_6_CN20PV2_I814_N2: length 70.4
  TOP w0.203: R521.2 74.05,57.64 75.76,57.64 77.48,55.93 v1(79.83,55.93) 82.94,55.93 84.02,57 R520.2
  TOP w0.394: P504.4 v1(44.74,80.47)
  L10_SIG w0.114: v1(44.74,80.47) 44.74,79.9 46.55,78.09 46.55,64.11 46.55,64.11 46.55,63.68 46.55,63.68 46.55,63.49 50.56,59.48 74.69,59.48 78.24,55.93 v1(79.83,55.93)
UNNAMED_6_CN20PV2_I814_N3: length 68.8
  TOP w0.305: v1(90.43,49.43) 90.41,49.43 90.3,49.31 90.22,49.31 90.14,49.23 89.67,49.23
  TOP w0.394: P504.6 v1(46.01,80.51)
  L10_SIG w0.114: v1(90.43,49.43) 90.06,49.8 90.06,54.4 88.29,56.18 83.45,56.18 79.01,60.62 56.53,60.62 55.13,62.02 55.13,65.83 53.86,67.1 53.86,73.45 47.51,79.8 46.71,79.8 v1(46.01,80.51)
UNNAMED_6_CN20PV2_I814_N4: length 56.5
  TOP w0.203: v1(87.39,60.37) 87.39,58.43 R523.2
  TOP w0.394: P504.8 v1(47.28,80.51)
  L10_SIG w0.114: v1(47.28,80.51) 49.73,80.51 62.26,67.97 77.63,67.97 80.02,65.58 80.02,62.1 81.75,60.37 v1(87.39,60.37)
UNNAMED_6_CN20PV2_I814_N8: length 52
  TOP w0.203: R524.2 91.29,58.75 85.99,64.05 v1(85.99,64.56)
  TOP w0.394: P504.16 v1(52.36,80.51)
  L10_SIG w0.114: v1(52.36,80.51) 59.8,73.07 69.61,73.07 72.78,69.9 78.24,69.9 82.05,66.09 84.46,66.09 v1(85.99,64.56)
UNNAMED_7_AD7291_I1067_DCAP: length 2.6
  TOP w0.305: C651.1 44.46,22.91 45.35,22.91 45.73,23.29 U601.8
UNNAMED_7_AD7291_I1067_VIN0: length 5.2
  TOP w0.305: U601.18 51.2,23.29 51.58,22.91 52.09,22.91 R603.1 R602.1
UNNAMED_7_AD7291_I1067_VIN1: length 4.5
  TOP w0.305: U601.19 52.88,23.79 52.89,23.8 53.48,23.8 ; R604.2 53.48,23.8 ; 53.48,23.8 R605.2
UNNAMED_7_AD7291_I1067_VIN2: length 5.2
  TOP w0.305: R607.2 R606.2 52.09,24.69 51.19,24.69 50.79,24.29 U601.20
UNNAMED_7_AD7291_I1067_VIN3: length 4.6
  TOP w0.305: U601.1 49.52,26.06 50.43,26.98 R608.2 R609.2
UNNAMED_7_AD7291_I1067_VIN5: length 4.4
  TOP w0.305: U601.3 48.52,26.46 48.91,26.85 R611.2 R610.2
UNNAMED_7_AD7291_I1067_VIN7: length 4.9
  TOP w0.305: U601.5 47.52,26.33 R613.2 R612.2
UNNAMED_7_AD7291_I1067_VREF: length 2.3
  TOP w0.305: U601.7 45.74,23.79 45.6,23.92 45.01,23.92 C650.1
UNNAMED_7_AD9370V2_I936_VCLKVCO: length 1.2
  TOP w0.254: v2(38.04,41.18) U101.M1
  BOTTOM w0.305: v2(38.04,41.18) 38.06,41.2 C644.1
UNNAMED_7_AD9370V2_I936_VDDABB: length 10.6
  TOP w0.254: v2(31.64,44.38) U101.E5
  L12_PWR w0.394: v2(31.64,44.38) 31.38,44.12 31.38,42.34 v4(33.03,40.69) v4(33.41,40.31) v4(33.41,39.7)
  BOTTOM w0.305: C606.1 31.99,44.36 v2(31.64,44.38)
  BOTTOM w0.394: v4(33.03,40.69) v4(33.41,40.31) v4(33.41,39.7)
  BOTTOM w0.508: R614.1 33.7,39.4 v4(33.41,39.7) ; v2(31.64,44.38) 31.25,43.99 C604.1
UNNAMED_7_AD9370V2_I936_VDDARXR: length 7.6
  TOP w0.254: U101.B1 v2(29.24,41.18)
  L12_PWR w0.394: v4(28.71,38.76) 28.71,37.51 28.1,36.9 28.1,36.34 v3(28.71,35.73)
  BOTTOM w0.305: v2(29.24,41.18) 29.23,41.17 C605.1
  BOTTOM w0.394: R615.1 v3(28.71,35.73) ; C605.1 28.9,40.23 C603.1 28.71,39.28 v4(28.71,38.76)
UNNAMED_7_AD9370V2_I936_VRXVCOL: length 1.2
  TOP w0.254: U101.C8 v2(30.04,46.78)
  BOTTOM w0.305: v2(30.04,46.78) 30.03,46.78 C645.1
UNNAMED_7_AD9370V2_I936_VSNRXVC: length 0.8
  TOP w0.254: v2(30.04,42.78) U101.C3
  BOTTOM w0.508: v2(30.04,42.78) 30.04,42.78 C646.1
UNNAMED_7_AD9370V2_I936_VTXVCOL: length 13.7
  TOP w0.254: U101.F13 v6(32.44,51.58)
  L10_SIG w0.305: v6(32.44,51.58) 32.78,51.91 33.24,51.91 33.64,52.31
  L10_SIG w0.508: 33.64,52.31 34.05,52.71 34.05,58.21 36.9,61.07 v1(36.9,61.78)
  BOTTOM w0.394: v1(36.9,61.78) C647.1
UNNAMED_8_ADP125_I911_ADJ: length 3.1
  TOP w0.254: R740.2 R739.1 50.34,15.34 U702.3
UNNAMED_8_ADP5054_I118_BST1: length 2
  TOP w0.394: v1(83.45,26.62) 83.46,26.61 C713.1
  BOTTOM w0.203: U701.32 v1(83.45,26.62)
UNNAMED_8_ADP5054_I118_BST2: length 1.9
  TOP w0.394: v1(83.56,24.62) 83.58,24.6 C715.2
  BOTTOM w0.254: U701.28 v1(83.56,24.62)
UNNAMED_8_ADP5054_I118_BST3: length 2
  TOP w0.394: v1(92.4,28.62) 92.53,28.75 C717.1
  BOTTOM w0.254: U701.1 v1(92.4,28.62)
UNNAMED_8_ADP5054_I118_BST4: length 1.7
  BOTTOM w0.254: U701.12 92.86,23.12 C719.1
UNNAMED_8_ADP5054_I118_COMP1: length 2.8
  BOTTOM w0.254: U701.40 86.75,30.08 86.74,30.09 86.74,30.88 87.62,31.76 R704.2
UNNAMED_8_ADP5054_I118_COMP2: length 2.2
  BOTTOM w0.254: U701.20 87.25,21.28 86.63,20.66 R707.2
UNNAMED_8_ADP5054_I118_COMP3: length 2.8
  BOTTOM w0.203: R708.2 90.94,31.7 90.94,30.56 90.27,29.89 90.27,29.85 90.25,29.83 U701.47
UNNAMED_8_ADP5054_I118_COMP4: length 2.1
  BOTTOM w0.254: R711.2 90,20.87 89.75,21.12 U701.15
UNNAMED_8_ADP5054_I118_DL1: length 5.3
  TOP w0.394: R718.2 82.31,24.22 v1(82.33,24.19)
  BOTTOM w0.203: v1(82.33,24.19) 82.99,24.85 82.99,25.76 83.3,26.06 83.94,26.06 83.99,26.12 U701.31
  BOTTOM w0.254: v1(82.33,24.19) 82.31,24.22 Q701.5
UNNAMED_8_ADP5054_I118_DL2: length 8.9
  TOP w0.394: v1(78.55,24.22) 81.17,26.84 R719.2 82.43,26.71 83.55,25.59 v1(83.55,25.46)
  BOTTOM w0.203: v1(83.55,25.46) 83.9,25.12 U701.29
  BOTTOM w0.254: Q701.2 v1(78.55,24.22)
UNNAMED_8_ADP5054_I118_EN1: length 48.1
  L5_SIG w0.394: P702.2 69.13,33.55 72.34,30.34 81.23,30.34 82.68,31.79 84.92,31.79 v1(85.59,31.13) 86.69,30.02 90.18,30.02 91.07,30.91 91.07,31.42 91.58,31.92 93.1,31.92 94.5,30.53 94.5,24.68 92.21,22.4 90.81,22.4 90.36,21.95 v1(90.36,21.4)
  BOTTOM w0.254: U701.39 86.25,30.46 v1(85.59,31.13) R705.2 R706.1 ; C711.2 91.03,20.73 v1(90.36,21.4) 90.25,21.51 U701.14
UNNAMED_8_ADP5054_I118_EN2: length 51.8
  TOP w0.305: P702.1 73.33,32.53 R702.2
  TOP w0.394: R703.1 86.87,20.73 86.87,21.29 v1(86.65,21.5)
  L5_SIG w0.394: v1(86.65,21.5) 86.65,21.04 85.84,20.23 83.12,20.23 80.78,22.57 80.78,23.03 77.1,26.72 69.61,26.72 66.92,29.41 64.58,29.41 63.64,30.35 63.64,34.08 65.8,36.25 69.62,36.25 P702.1
  BOTTOM w0.254: v1(86.65,21.5) 86.75,21.6 U701.21
UNNAMED_8_ADP5054_I118_EN3: length 35.8
  L5_SIG w0.394: P702.3 71.53,29.26 81.45,29.26 82.43,30.24 84.75,30.24 85.73,29.26 91.07,29.26 91.95,30.14 v1(91.95,31.03)
  BOTTOM w0.203: 90.94,29.76 90.94,29.64 90.75,29.44 U701.48
  BOTTOM w0.254: R712.1 66.6,34.2 P702.3
  BOTTOM w0.394: C712.2 R710.1 R709.2 v1(91.95,31.03) 91.95,30.77 90.94,29.76
UNNAMED_8_ADP5054_I118_FB1: length 37.9
  TOP w0.394: v1(87.72,31.03) 87.72,31.08 87.72,31.08 87.72,31.94 86.92,32.74 R714.1 R716.1 84.3,34.49 83.91,34.89 83.9,34.89 82.35,36.44 76.21,36.44 74.41,34.63 v1(74.41,34)
  L5_SIG w0.394: v1(87.72,31.03) 87.72,31.03 87.56,31.03 85.78,32.81 75.59,32.81 v1(74.41,34)
  BOTTOM w0.254: v1(87.72,31.03) 87.72,30.88 87.25,30.4 U701.41
  BOTTOM w0.508: R717.1 74.05,31.81 74.41,32.17 R715.1 v1(74.41,34)
UNNAMED_8_ADP5054_I118_FB2: length 25.6
  TOP w0.394: v1(87.59,19.19) R720.2 R723.1
  BOTTOM w0.203: v1(87.59,19.19) 87.59,20.43 87.75,20.59 U701.19
  BOTTOM w0.508: R722.1 74.31,16.27 74.66,15.91 R721.1 74.66,14.62 75.2,14.08 85.64,14.08 87.52,15.96 87.52,19.11 v1(87.59,19.19)
UNNAMED_8_ADP5054_I118_FB3: length 13
  TOP w0.394: v1(90.28,31.13) 92.02,32.87 R724.2 R727.1 96.29,33.85 v1(96.55,34.1)
  BOTTOM w0.203: U701.46 89.75,30.08 90.28,30.62 v1(90.28,31.13)
  BOTTOM w0.508: R726.1 96.91,32.78 97.45,33.31 R725.1 v1(96.55,34.1)
UNNAMED_8_ADP5054_I118_FB4: length 21.3
  TOP w0.394: v1(89.17,20.43) 89.18,20.45 R728.2 92.43,20.45 R731.1
  BOTTOM w0.203: v1(89.17,20.43) 89.25,20.52 U701.16
  BOTTOM w0.254: 89.09,18.4 89.17,18.48 v1(89.17,20.43)
  BOTTOM w0.508: 89.09,18.4 89.09,16.32 90.36,15.05 96.89,15.05 97.42,15.58 R729.1 97.42,17.11 96.91,17.61 R730.1
UNNAMED_8_ADP5054_I118_PWRGD: length 31.5
  L5_SIG w0.508: v1(66.56,31.42) 67.54,31.42 71.05,27.91 77.18,27.91 81.6,23.48 83.63,23.48 84.59,22.53 86.62,22.53 87.39,21.76 87.39,20.56 v1(88.53,19.42)
  BOTTOM w0.203: U701.17 88.75,21.01 88.53,20.79 v1(88.53,19.42)
  BOTTOM w0.394: v1(66.56,31.42) R712.2
UNNAMED_8_ADP5054_I118_RT: length 2.8
  BOTTOM w0.203: U701.42 87.75,30.19 88.28,30.72 88.28,30.8 88.28,30.8 88.28,31.42 88.63,31.77 R713.1
UNNAMED_8_ADP5054_I118_SW11: length 6.4
  TOP w0.394: v1(83.32,27.44) v1(83.32,28.08) 83.53,27.88 C713.2
  BOTTOM w0.254: 79.84,25.9 79.6,25.65 Q701.3 79.81,24.87 80,24.68 Q701.PAD2 ; v1(83.32,27.44) 83.48,27.44 83.8,27.12 U701.33 ; U701.35 83.36,28.12 v1(83.32,28.08)
UNNAMED_8_ADP5054_I118_SW21: length 6.2
  TOP w0.394: C715.1 82.97,22.44 v1(82.64,22.11) v1(82.64,22.77)
  BOTTOM w0.254: Q701.6 81.11,23.57 80.93,23.75 Q701.PAD1 ; Q701.6 82.17,23.57 82.38,23.36 ; Q701.6 81.42,22.85 ; U701.25 83.86,23.12 ; 83.58,23.81 83.89,24.12 U701.27
UNNAMED_8_ADP5054_I118_SW31: length 4.7
  TOP w0.394: v1(93.13,26.58) v1(93.76,26.58) 93.45,26.9 C717.2
  BOTTOM w0.254: U701.5 93.09,26.62 v1(93.13,26.58) ; U701.4 92.87,27.12
UNNAMED_8_ADP5054_I118_SW41: length 3.3
  BOTTOM w0.254: 93.07,24.38 92.83,24.62 U701.9 ; 93.07,24.38 C719.2 ; 93.07,24.38 93.08,24.38 ; U701.8 92.53,25.12 92.9,24.75
UNNAMED_8_ADP5054_I118_VDD: length 2.9
  TOP w0.394: v1(88.89,31.03) 89.22,31.36 C703.2
  BOTTOM w0.203: v1(88.89,31.03) 88.89,30.7 88.25,30.06 U701.43
UNNAMED_8_CAP_I809_N2: length 2.1
  BOTTOM w0.762: R732.1 68.02,31.05 C724.2
UNNAMED_8_CAP_I814_N2: length 2.1
  BOTTOM w0.762: C727.2 68.45,22.69 R733.1
UNNAMED_8_CAP_I872_N2: length 2.2
  BOTTOM w0.762: R737.1 C731.2
UNNAMED_8_CAP_I936_N2: length 3.5
  BOTTOM w0.762: C729.2 106.75,30.59 108.45,28.9 R734.1
UNNAMED_8_CAP_I967_N1: length 2
  BOTTOM w0.508: R729.2 98.69,17.06 99.2,17.56 C720.1
UNNAMED_8_CAP_I970_N1: length 2.1
  BOTTOM w0.508: R725.2 98.72,33.31 99.2,32.83 C718.1
UNNAMED_8_CAP_I971_N1: length 2
  BOTTOM w0.508: C716.1 76.34,16.14 75.93,15.74 R721.2
UNNAMED_8_CAP_I974_N1: length 2
  BOTTOM w0.508: R715.2 75.68,32.14 76.09,31.74 C714.1
UNNAMED_8_CAP_I985_N2: length 1
  BOTTOM w0.381: C704.2 R704.1
UNNAMED_8_CAP_I986_N2: length 1
  BOTTOM w0.381: C706.2 R707.1
UNNAMED_8_CAP_I989_N2: length 1
  BOTTOM w0.394: R708.1 C708.2
UNNAMED_8_CAP_I990_N2: length 1
  BOTTOM w0.394: R711.1 C710.2
UNNAMED_8_CN2P_I1027_N1: length 5.3
  TOP w0.508: P701.1 112.53,22.27 ; P701.1 111.2,20.94 ; P701.1 111.2,23.61 ; P701.1 109.86,22.27
UNNAMED_8_DIOLED_I983_N: length 1.9
  TOP w0.203: R701.2 123.21,14.18 DS701.C
UNNAMED_8_DIOLED_I1004_P: length 2
  TOP w0.508: R735.2 DS702.A
UNNAMED_9_CAP_I337_N1: length 1.5
  TOP w0.203: C801.1 142.91,48.02 v2(142.91,47.88)
  BOTTOM w0.203: v2(142.91,47.88) P801.B20
UNNAMED_9_CAP_I338_N1: length 1.7
  TOP w0.203: v2(141.67,47.84) 142.2,48.37 C802.1
  BOTTOM w0.203: P801.B21 141.68,47.84
  BOTTOM w0.394: 141.68,47.84 v2(141.67,47.84)
UNNAMED_9_CAP_I852_N2: length 1.4
  TOP w0.203: C806.2 139.12,68.54 v2(139.12,68.22)
  BOTTOM w0.203: P801.D5 139.74,67.6 v2(139.12,68.22)
UNNAMED_9_CAP_I853_N2: length 1.5
  TOP w0.203: v2(140.36,68.17) 140.36,68.55 C805.2
  BOTTOM w0.203: v2(140.36,68.17) 139.74,68.8 P801.D4
UNNAMED_9_CN400PAK_I293_N2: length 1.5
  TOP w0.305: v2(134.02,70.74) 133.69,71.07 R801.2
  BOTTOM w0.203: v2(134.02,70.74) P801.H2
UNNAMED_9_CN400PAK_I293_N10: length 1.5
  TOP w0.394: R802.2 v2(135.29,60.58)
  BOTTOM w0.203: P801.H10 v2(135.29,60.58)
UNNAMED_9_CN400PAK_I293_N11: length 1.5
  TOP w0.394: R803.2 v2(135.29,59.31)
  BOTTOM w0.203: v2(135.29,59.31) P801.H11
UNNAMED_9_CN400PAK_I293_N13: length 1.5
  TOP w0.394: R804.2 v2(134.02,56.77)
  BOTTOM w0.203: v2(134.02,56.77) P801.H13
UNNAMED_9_CN400PAK_I293_N14: length 1.5
  TOP w0.394: R805.2 v2(135.29,56.77)
  BOTTOM w0.203: P801.H14 v2(135.29,56.77)
UNNAMED_9_CN400PAK_I296_N12: length 1.6
  TOP w0.203: v2(135.29,58.04) 135.43,58.18 R806.2
  BOTTOM w0.203: P801.G12 v2(135.29,58.04)
UNNAMED_9_CN400PAK_I297_N18: length 75.8
  L8_SIG w0.114: v1(74.76,61.54) 74.94,61.72 74.94,62.98 75.57,63.61 85.54,63.61 86.75,62.4 96.66,62.4 106.91,52.15 135.23,52.15 136.21,51.17 136.84,51.17 137.59,50.42 v2(141.64,50.42)
  BOTTOM w0.203: R816.2 74.3,61.29 74.56,61.54 v1(74.76,61.54) ; v2(141.64,50.42) P801.C18
UNNAMED_9_CN400PAK_I297_N19: length 71.5
  L8_SIG w0.114: v1(77.33,61.54) 77.86,61.01 94.5,61.01 104.66,50.85 125.49,50.85 126.12,50.21 126.94,50.21 126.95,50.2 127.37,50.2 127.38,50.21 128.15,50.21 128.5,50.56 130.09,50.56 130.93,49.72 141.07,49.72 v2(141.64,49.15)
  BOTTOM w0.203: R817.2 76.84,61.06 v1(77.33,61.54) ; v2(141.64,49.15) P801.C19
UNNAMED_9_CN400PAK_I298_N11: length 1.6
  TOP w0.394: R810.2 140.68,59.61 v2(140.37,59.31)
  BOTTOM w0.203: P801.D11 v2(140.37,59.31)
UNNAMED_9_CN400PAK_I298_N14: length 1.5
  TOP w0.305: R811.2 140.38,55.49 v2(140.37,55.5)
  BOTTOM w0.203: P801.D14 v2(140.37,55.5)
UNNAMED_9_CN400PAK_I298_N15: length 1.5
  TOP w0.305: R812.2 140.38,54.22 v2(140.37,54.23)
  BOTTOM w0.203: P801.D15 v2(140.37,54.23)
UNNAMED_9_CN400PAK_I298_N17: length 72.3
  L8_SIG w0.114: v2(139.1,52.96) 137.34,54.72 108.76,54.72 97.72,65.76 97.72,65.78 96.66,66.85 83.83,66.85 83.07,67.61 76.16,67.61 v1(74.96,66.42)
  BOTTOM w0.203: v2(139.1,52.96) P801.D17 ; R813.2 v1(74.96,66.42)
UNNAMED_9_CN400PAK_I298_N18: length 69.3
  L8_SIG w0.114: v2(139.1,51.69) 138.23,51.69 136.28,53.64 123.71,53.64 123.7,53.65 123.27,53.65 123.26,53.64 107.96,53.64 95.26,66.34 77.59,66.34 v1(77.56,66.32)
  BOTTOM w0.203: v1(77.56,66.32) 77.46,66.42 R814.2 ; v2(139.1,51.69) P801.D18
UNNAMED_9_CN400PAK_I299_N1: length 3.2
  TOP w0.394: R807.2 135.12,74.72 v2(136.56,73.28)
  BOTTOM w0.394: P801.F1 v2(136.56,73.28)
UNNAMED_9_ICM24CXX_I809_E2: length 4.1
  TOP w0.305: U801.3 116.5,30.65 116.07,30.21 115.97,30.21 115.63,29.87 R823.2 R822.1
VCON: length 5.5
  BOTTOM w0.394: R407.2 123.62,76.52 123.61,76.5 C404.1 Y402.1 Y403.1 Y401.1
VCXO_CTRL: length 42
  L5_SIG w0.114: v1(126.07,76.52) 111.53,76.52 103.19,68.17 90.46,68.17 v1(89.88,67.59)
  BOTTOM w0.254: U401.8 90.04,68.13 90.04,67.75 v1(89.88,67.59)
  BOTTOM w0.394: R407.1 v1(126.07,76.52)
VCXO_IN+: length 15.8
  L10_SIG w0.091: v1(95.63,64.79) 95.63,63.49 95.3,63.17 90.33,63.17 89.83,62.66 88.51,62.66 88.42,62.76 88.42,63.01 v1(88.76,63.36)
  BOTTOM w0.203: C409.2 v1(95.63,64.79) ; v1(88.76,63.36) 88.47,63.65 88.47,67.71 88.54,67.78 88.54,68.07 U401.11
VCXO_IN-: length 15.8
  L10_SIG w0.091: v1(95.63,61.79) 95.63,62.65 95.36,62.91 90.43,62.91 89.93,62.41 88.4,62.41 88.16,62.65 88.16,62.94 v1(87.74,63.36)
  BOTTOM w0.203: U401.12 88.04,68 88.04,67.78 88.11,67.71 88.11,63.73 v1(87.74,63.36) ; C407.2 v1(95.63,61.79)
VOUT1_1V3_ANLG: length 81.5
  TOP w0.305: v1(41.67,32.44) 42.55,32.44 44.08,30.91 44.08,29.52 R612.1
  TOP w0.508: R716.2 82.18,32.74 77.6,28.16 P703.1
  TOP w0.762: C602.1 63.45,29.76 P703.1 65.23,27.99 C601.1
  L8_SIG w0.508: 65.06,27.08 P703.1 ; P703.1 66.14,28.16 ; P703.1 65.06,29.24 ; P703.1 63.98,28.16
  L12_PWR w0.394: v3(29.22,32.56) 29.47,32.3 29.47,30.7 29.31,30.54 29.31,29.99 29.47,29.83 29.47,27.73
  BOTTOM w0.305: E603.1 42.43,41.7 42,41.7 v3(41.87,41.58) ; v1(41.67,32.44) 41.78,32.33
  BOTTOM w0.394: E610.1 v1(10.03,59.79) ; E608.1 v1(12.71,50.85) ; R601.1 52.71,26.97 54.43,28.69 54.43,29.25 54.01,29.67 ; v3(36.45,39.41) v3(35.95,38.91) 35.57,38.53 v3(35.57,38.41) ; v3(29.22,32.56) 29.22,33.33 28.71,33.84 ; E612.1 v1(10.04,62.78) ; E611.1 v1(9.98,54.21) ; E607.1 v1(9.03,42.97)
  BOTTOM w0.508: v1(32.39,29.64) v1(32.39,28.88) ; 63.98,28.16 P703.1 ; P703.1 65.06,29.24 ; P703.1 65.06,27.08 ; P703.1 66.14,28.16 ; E605.1 15.12,40.81 14.49,41.45 v1(13.6,41.45) ; v1(21.22,28.75) 21.47,29.06 21.47,29.67 21.47,30.16 E609.1 ; R614.2 v3(35.57,38.41) ; E604.1 v1(44.56,39.49) ; E606.1 44.6,33.08 43.85,32.33 41.76,32.33
  BOTTOM w0.762: E601.1 54.01,29.67 ; E613.1 59.73,29.67
  vias: v1(40.99,32.44) v1(41,33.1) v1(41.67,33.1) v1(61.35,28.49) v1(61.35,27.73) v1(62.24,28.49) v1(62.24,27.73) v1(63.13,28.49) v1(63.13,27.73)
VOUT2_1V3_DIG: length 110
  TOP w0.254: v2(37.24,46.78) U101.L8 v2(37.24,47.58) U101.L9 v2(37.24,48.38)
  TOP w0.305: P704.1 64.24,23.04 R604.1
  TOP w0.508: v1(70.65,19.67) v1(69.76,19.67) v1(68.87,19.67) v1(67.98,19.67) v1(67.98,18.91) v1(68.87,18.91) v1(69.76,18.91) v1(70.65,18.91) 71.64,17.92 R723.2
  TOP w1.27: C638.1 65.12,22.27 P704.1
  L5_SIG w0.508: 66.14,22.21 P704.1 65.06,21.13
  L5_SIG w1.905: P704.1 63.57,22.21 56.52,29.26 55.25,29.26 51.95,32.56 47.74,32.56 v1(47.21,32.03) v1(47.21,32.94) v1(48.27,32.94)
  L8_SIG w0.508: 63.98,22.21 P704.1 ; P704.1 65.06,21.13 ; P704.1 66.14,22.21 ; P704.1 65.06,23.29
  L12_PWR w0.635: v2(37.24,47.58) v2(37.24,48.38)
  L12_PWR w1.016: v2(37.24,47.58) v2(37.24,46.78) 38.25,45.77 40.27,45.77
  L12_PWR w1.27: 49.16,40.05 48.9,40.31 48.9,42.21 46.23,44.88 41.16,44.88 40.27,45.77
  L12_PWR w1.905: v1(48.27,32.94) v1(48.27,32.05) 48.25,32.03 v1(47.21,32.03) v1(47.21,32.94) v1(48.27,32.94) ; v1(48.27,32.94) 49.16,33.83 49.16,40.05
  BOTTOM w0.305: C636.1 37.86,45.98 C637.1 37.55,47.08 v2(37.24,46.78) v2(37.24,47.58) v2(37.24,48.38)
  BOTTOM w0.508: 65.06,21.13 P704.1 66.14,22.21
  BOTTOM w1.27: C639.1 65,22.27 P704.1 66.5,20.78 C727.1
VOUT3_3V3: length 117.9
  TOP w0.254: v2(29.24,52.38) U101.B14
  TOP w0.305: R608.1 v1(50.43,30.4)
  TOP w0.394: v2(133.42,74.98) R807.1
  TOP w0.508: R727.2 98.73,32.87 99.61,31.99 v1(101.51,31.99) v1(102.27,31.99) ; R735.1 v1(103.04,31.99) 103.42,32.37 P705.1
  L3_PWR w0.508: 102.34,34.18 P705.1 ; P705.1 103.42,33.1 ; P705.1 103.42,35.26 ; P705.1 104.5,34.18
  L10_SIG w0.203: v1(59.45,21.38) 59.45,25.45 55.38,29.51 51.33,29.51 v1(50.43,30.4)
  L12_PWR w0.394: v1(101.51,31.99) v1(102.27,31.99) v1(103.04,31.99) 106.76,31.99 111.28,36.52 114.46,36.52 115.07,37.13 120.53,37.13 122.27,35.39 130.01,35.39 134.69,40.07 134.69,40.51 136.31,42.13 138.36,42.13 140.98,44.75 140.98,65.96 139.76,67.18 139.76,69.21 135.9,73.07 135.9,73.53 135.54,73.88 135.09,73.88 133.99,74.98 v2(133.42,74.98)
  BOTTOM w0.305: v2(29.24,52.38) 29.56,52.05 C641.1
  BOTTOM w0.508: P705.1 103.42,35.27 103.39,35.3 103.39,35.89 103.45,35.94 E706.1 ; P705.1 102.34,34.18 ; P705.1 104.5,34.18 ; P705.1 103.42,33.1
  vias: v1(57.41,21.38) v1(58.43,21.38) v1(58.47,20.11) v1(58.94,20.75) v1(59.45,20.11)
VOUT4_1V8: length 87.9
  TOP w0.203: v5(30.08,49.18) 30.84,49.18 ; C315.1 37.35,38.48
  TOP w0.254: 30.84,49.18 U101.D10
  TOP w0.394: L315.2 37.41,39.26 37.41,38.41 ; v1(37.41,37.85) 37.41,38.41 ; 37.41,38.41 37.35,38.48 ; v1(37.42,56.04) 37.41,56.02 C308.1 37.41,54.29 L308.1 ; v1(42.06,38.37) 42.61,38.37 v1(42.62,38.38) 43.17,38.38 v1(43.18,38.38) 44.84,36.72 44.84,32.56 47.13,30.27 47.13,29.52 R610.1 ; L307.2 32.27,54.29 32.27,55 ; v1(32.27,56.05) 32.27,55 ; 32.27,55 C307.1 ; L316.1 32.27,39.26 C316.1 v1(32.27,37.85)
  TOP w0.508: R731.2 95.36,19.18 96.26,18.28 v1(101.49,18.28) v1(102.17,18.28) v1(102.88,18.28)
  L3_PWR w0.203: 28.02,48.76 29.66,48.76 v5(30.08,49.18)
  L3_PWR w0.305: v1(32.27,56.05) 32.41,55.91 37.26,55.91 37.39,56.04 v1(37.42,56.04)
  L3_PWR w0.394: v1(32.27,37.85) 32.48,37.64 36.76,37.64 36.97,37.85 v1(37.41,37.85)
  L3_PWR w0.508: 103.42,15.16 P706.1 ; P706.1 102.34,16.24 ; P706.1 103.42,17.32 ; P706.1 104.5,16.24
  L3_PWR w0.762: 34.81,37.64 34.81,33.26 36.32,31.75 36.44,31.75 36.46,31.73 37.79,31.73 38.87,30.65 ; 34.81,55.91 34.81,57.32 33.92,58.21 33.92,68.12 33.41,68.63
  BOTTOM w0.305: v5(30.08,49.18) 30.22,49.32 C640.1
  BOTTOM w0.508: 102.34,16.24 P706.1 ; P706.1 103.42,17.32 ; P706.1 103.42,15.16 ; P706.1 104.5,16.24 ; 32.2,69.07 v1(32.2,69.78) ; 32.2,69.07 v1(32.21,69.07) ; 32.2,69.07 32.2,68.42 32.14,68.36 ; 32.14,68.36 v1(32.14,68.36) ; 32.14,68.36 32.14,66.21 C320.1 C321.1 32,62.45 L340.1 ; 42.68,37.45 C325.1 42.44,37.11 C326.1 40.83,37.11 40.83,37.11 40.14,37.11

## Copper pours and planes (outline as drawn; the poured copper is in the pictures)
AGND on TOP: 0,12.7 0,33.81 0.62,33.81 0.83,34.2 0.82,36.41 0.62,36.8 0,36.8 0,57.69 0.62,57.69 0.83,58.07 0.82,60.29 0.62,60.67 0,60.68 0,81.79 32.45,81.79 32.45,81.16 32.83,80.96 35.05,80.97 35.43,81.17 35.44,81.79 148.44,81.79 148.44,12.7 37.23,12.7 37.23,13.32 36.84,13.53 34.63,13.52 34.24,13.32 34.24,12.7 ; 8 cut-outs
AGND on BOTTOM: 0,12.7 0,21.87 0.58,21.87 0.79,22.26 0.78,24.48 0.58,24.86 0,24.86 0,45.75 0.58,45.75 0.79,46.13 0.78,48.35 0.58,48.73 0,48.74 0,69.63 0.58,69.63 0.79,70.01 0.78,72.23 0.58,72.61 0,72.61 0,81.79 20.39,81.79 20.39,81.21 20.77,81 22.99,81.01 23.37,81.21 23.38,81.79 148.44,81.79 148.44,12.7 23.38,12.7 23.38,13.28 22.99,13.49 20.77,13.48 20.39,13.28 20.39,12.7 ; 7 cut-outs
AGND on L2_GND: 0,12.7 0,81.79 148.44,81.79 148.44,12.7 ; 2 cut-outs
AGND on L3_PWR: 0,12.7 0,81.79 148.44,81.79 148.44,12.7 ; 1 cut-out
AGND on L4_GND, L6_GND, L9_GND, L11_GND, L12_PWR, L13_GND: 0,12.7 0,81.79 148.44,81.79 148.44,12.7
AGND on L5_SIG: 0,12.7 0,81.79 148.44,81.79 148.44,12.7 ; 31 cut-outs
AGND on L7_SIG: 0,12.7 0,81.79 148.44,81.79 148.44,12.7 ; 17 cut-outs
AGND on L8_SIG: 0,12.7 0,81.79 148.44,81.79 148.44,12.7 ; 18 cut-outs
AGND on L10_SIG: 0,12.7 0,81.79 148.44,81.79 148.44,12.7 ; 12 cut-outs
VDD_IF on TOP: 50.75,15.91 49.92,15.92 49.41,15.41 49.41,14.27 48.9,13.76 45.86,13.76 45.35,14.27 45.35,16.05 45.98,16.68 47.38,16.68 49.54,18.84 52.71,18.84 52.84,18.72 52.84,17.48 52.81,17.48 52.81,15.98 52.71,15.88 51.62,15.88 51.49,16.01 50.78,16.01 50.75,15.98
